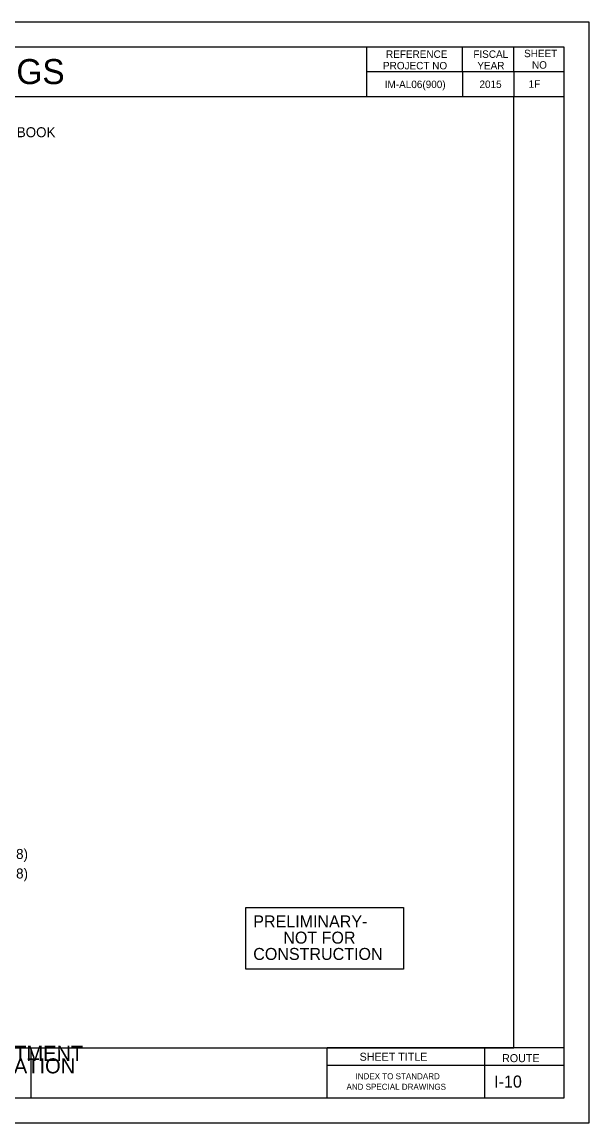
# Model space of a CAD drawing. Extents: x -12822 to 16384, y -6351 to 1913.
# Drawn here: x 283 to 850, y -6351 to -5251 of the extents above; entities that cross this region are included whole.
import ezdxf

# ---------------------------------------------------------------- set-up
doc = ezdxf.new("R2010")
doc.units = 0
for name, color, linetype in [('1', 7, 'Continuous'), ('ANNO-SHT', 7, 'Continuous'), ('ANNO-TXT', 7, 'Continuous'), ('Level 10', 7, 'Continuous'), ('Level 6', 7, 'Continuous'), ('Level 62', 7, 'Continuous'), ('SHT-BDR', 7, 'Continuous'), ('SHT-BNDRY', 7, 'Continuous')]:
    doc.layers.add(name, color=color, linetype=linetype)

msp = doc.modelspace()

# ---------------------------------------------------------------- linework, layer by layer
at = {"layer": '1'}
msp.add_lwpolyline([(507, -6135.5), (664.6, -6135.5), (664.6, -6197.2), (507, -6197.2)], close=True, dxfattribs=at)
at = {"layer": 'ANNO-TXT'}
for p, q in [((588.3, -6293.1), (745.9, -6293.1)), ((745.9, -6293.1), (825, -6293.1))]:
    msp.add_line(p, q, dxfattribs=at)
at = {"layer": 'Level 6'}
for p, q in [((627.7, -5275.8), (627.7, -5325.7)), ((723.5, -5300.8), (723.5, -5275.8)), ((775, -5300.1), (775, -5275.8)), ((825, -5300.5), (627.7, -5300.5)), ((723.5, -5300.8), (723.5, -5325.7)), ((775, -5300.1), (775, -5325.7)), ((825, -5325.7), (633.7, -5325.7)), ((825, -6275.7), (588.3, -6275.7))]:
    msp.add_line(p, q, dxfattribs=at)
at = {"layer": 'Level 62'}
msp.add_lwpolyline([(-850, -6350.8), (850, -6350.8), (850, -5250.8), (-850, -5250.8)], close=True, dxfattribs=at)
at = {"layer": 'SHT-BDR'}
msp.add_lwpolyline([(-725, -6275.7), (775, -6275.7), (775, -5325.7), (-725, -5325.7)], close=True, dxfattribs=at)
at = {"layer": 'SHT-BNDRY'}
for p, q in [((292.3, -6325.8), (292.3, -6275.7)), ((588.3, -6325.8), (588.3, -6275.7)), ((745.9, -6325.8), (745.9, -6275.7))]:
    msp.add_line(p, q, dxfattribs=at)
msp.add_lwpolyline([(-787.5, -6325.8), (825, -6325.8), (825, -5275.8), (-787.5, -5275.8)], close=True, dxfattribs=at)

# ---------------------------------------------------------------- texts
at = {"layer": '1'}
for s, p in [('PRELIMINARY-', (514.4, -6155.4)), ('NOT FOR', (544.4, -6171.6)), ('CONSTRUCTION', (514.4, -6187.9))]:
    msp.add_text(s, height=12, dxfattribs=at).set_placement(p)
at = {"layer": 'ANNO-SHT'}
for s, height, p in [('INDEX TO STANDARD AND SPECIAL DRAWINGS', 24.997, (-448.6, -5312.8)), ('IM-AL06(900)', 7.449, (645.8, -5316.8)), ('2015', 7.45, (740.5, -5316.7)), (' 1F ', 7.45, (786.9, -5316.4)), ('INDEX TO STANDARD', 6, (616.6, -6307.1)), ('AND SPECIAL DRAWINGS', 6, (607.6, -6317.6)), ('  I-10  ', 12, (746.3, -6315.4))]:
    msp.add_text(s, height=height, dxfattribs=at).set_placement(p)
at = {"layer": 'ANNO-TXT'}
for s, p in [('ALABAMA DEPARTMENT', (106, -6288.7)), ('OF TRANSPORTATION', (118, -6301.2))]:
    msp.add_text(s, height=15, rotation=360, dxfattribs=at).set_placement(p)
for s, p in [('SHEET TITLE', (620.7, -6288.6)), ('ROUTE', (763.1, -6290))]:
    msp.add_text(s, height=8, dxfattribs=at).set_placement(p)
at = {"layer": 'Level 10'}
for s, p in [('ALABAMA DEPARTMENT OF TRANSPORTATION SPECIAL AND STANDARD HIGHWAY DRAWINGS BOOK', (-348.3, -5365.9)), ('STANDARD BARRIER RAIL EXTENSION FOR BRIDGES SKEWED 15 DEGREES AND GREATER SHEET 1 OF 2 (SHEET 4 OF 8)', (-502.1, -6087)), ('STANDARD BARRIER RAIL EXTENSION FOR BRIDGES SKEWED 15 DEGREES AND GREATER SHEET 1 OF 2 (SHEET 5 OF 8)', (-502.1, -6106.5))]:
    msp.add_text(s, height=10, dxfattribs=at).set_placement(p)
at = {"layer": 'Level 6'}
for s, p in [('REFERENCE', (647.1, -5286.6)), ('FISCAL', (734.4, -5286.6)), ('SHEET', (785.1, -5285.9)), ('PROJECT NO', (644.1, -5298.1)), ('YEAR', (738.4, -5298.1)), ('NO', (793, -5297.4))]:
    msp.add_text(s, height=7.44, dxfattribs=at).set_placement(p)

doc.saveas('drawing.dxf')
